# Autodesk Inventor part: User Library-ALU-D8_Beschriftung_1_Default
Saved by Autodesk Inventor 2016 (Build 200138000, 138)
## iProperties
Created: 2012-01
Part Number: User Library-ALU-D8_Beschriftung_1_Default
Document SubType Name: Modeling
Designer: Trevor
Density: 1 g/cm^3
Material: Generic
Appearance: Glossy - Black
Author: Trevor
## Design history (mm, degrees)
feature "Base1"
node "Imported1"
